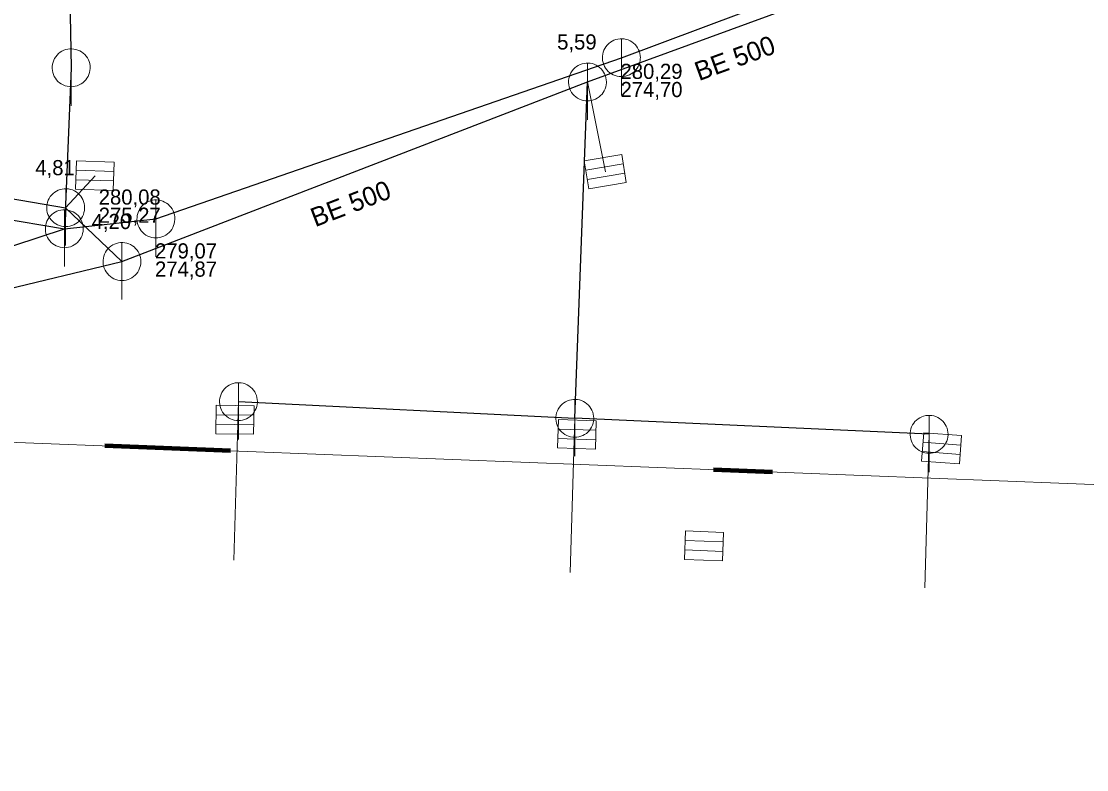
# Model space of a CAD drawing. Extents: x -725153 to -724843, y -978146 to -977794.
# Drawn here: x -725015.4 to -724959.2, y -977881.9 to -977842.4 of the extents above; entities that cross this region are included whole.
import ezdxf

# ---------------------------------------------------------------- set-up
doc = ezdxf.new("R2010")
doc.units = 0
doc.header["$LTSCALE"] = 0.32
doc.layers.add('1', color=7, linetype='Continuous')
for name, color, linetype, lineweight in [('11', 7, 'Continuous', 13), ('13', 7, 'Continuous', 13), ('14', 7, 'Continuous', 25), ('22', 7, 'Continuous', 13), ('3', 7, 'Continuous', 106)]:
    doc.layers.add(name, color=color, linetype=linetype, lineweight=lineweight)

msp = doc.modelspace()

# ---------------------------------------------------------------- linework, layer by layer
at = {"layer": '11'}
for p, q in [((-724984.587, -977850.34), (-724985.539, -977845.6)), ((-725011.522, -977850.547), (-725013.07, -977852.23)), ((-725004.203, -977870.821), (-725003.953, -977862.46)), ((-724986.446, -977871.468), (-724986.209, -977863.341)), ((-724967.733, -977872.279), (-724967.516, -977864.182))]:
    msp.add_line(p, q, dxfattribs=at)
at = {"layer": '13'}
msp.add_lwpolyline([(-724953.059, -977881.873), (-724953.002, -977867.059), (-725028.727, -977864.108)], dxfattribs=at)
at = {"layer": '14'}
for p, q in [((-725013.329, -977813.52), (-725012.78, -977844.85)), ((-724983.75, -977844.32), (-724941.885, -977828.658)), ((-725012.78, -977844.85), (-725013.14, -977853.34)), ((-725042.36, -977847.23), (-725013.07, -977852.23)), ((-725042.11, -977848.46), (-725013.14, -977853.34)), ((-725029.859, -977859.828), (-725010.1, -977855.07)), ((-725003.953, -977862.46), (-724986.209, -977863.341))]:
    msp.add_line(p, q, dxfattribs=at)
for points in [[(-724985.54, -977845.6), (-724969.507, -977839.725), (-724959.646, -977836.111)], [(-725013.14, -977853.34), (-725008.31, -977852.82), (-724983.75, -977844.32)], [(-725013.07, -977852.23), (-725010.1, -977855.07), (-724985.54, -977845.6)], [(-724967.516, -977864.182), (-724986.209, -977863.341), (-724985.54, -977845.6)], [(-725065.126, -977858.647), (-725045.825, -977859.261), (-725028.018, -977858.237), (-725013.14, -977853.34)]]:
    msp.add_lwpolyline(points, dxfattribs=at)
at = {"layer": '22'}
for p, q in [((-724983.75, -977846.32), (-724983.749, -977843.32)), ((-725012.78, -977846.85), (-725012.779, -977843.85)), ((-724985.54, -977847.6), (-724985.539, -977844.6)), ((-724985.626, -977850.253), (-724983.653, -977849.924)), ((-725012.54, -977850.757), (-725010.541, -977850.822)), ((-725012.524, -977850.257), (-725010.525, -977850.322)), ((-724985.544, -977850.746), (-724983.571, -977850.417)), ((-725013.07, -977854.23), (-725013.069, -977851.23)), ((-725008.31, -977854.82), (-725008.309, -977851.82)), ((-725013.14, -977855.34), (-725013.139, -977852.34)), ((-725010.1, -977857.07), (-725010.099, -977854.07)), ((-725003.953, -977864.46), (-725003.952, -977861.46)), ((-724986.209, -977865.341), (-724986.208, -977862.341)), ((-725005.139, -977863.151), (-725003.139, -977863.177)), ((-725005.146, -977863.651), (-725003.146, -977863.677)), ((-724967.516, -977866.182), (-724967.515, -977863.182)), ((-724987.09, -977863.905), (-724985.091, -977863.968)), ((-724987.106, -977864.405), (-724985.107, -977864.468)), ((-724967.839, -977864.6), (-724965.844, -977864.749)), ((-724967.876, -977865.099), (-724965.881, -977865.248)), ((-724980.383, -977869.782), (-724978.384, -977869.86)), ((-724980.402, -977870.281), (-724978.404, -977870.36))]:
    msp.add_line(p, q, dxfattribs=at)
for points in [[(-724982.75, -977844.32), (-724982.755, -977844.211), (-724982.773, -977844.103), (-724982.803, -977843.997), (-724982.843, -977843.896), (-724982.895, -977843.799), (-724982.957, -977843.709), (-724983.029, -977843.626), (-724983.109, -977843.552), (-724983.197, -977843.486), (-724983.291, -977843.431), (-724983.391, -977843.386), (-724983.496, -977843.353), (-724983.603, -977843.331), (-724983.712, -977843.321), (-724983.822, -977843.323), (-724983.93, -977843.337), (-724984.037, -977843.362), (-724984.14, -977843.399), (-724984.238, -977843.448), (-724984.33, -977843.506), (-724984.416, -977843.575), (-724984.493, -977843.652), (-724984.562, -977843.738), (-724984.621, -977843.83), (-724984.669, -977843.928), (-724984.706, -977844.031), (-724984.732, -977844.138), (-724984.746, -977844.246), (-724984.749, -977844.356), (-724984.739, -977844.465), (-724984.718, -977844.572), (-724984.684, -977844.676), (-724984.64, -977844.776), (-724984.585, -977844.871), (-724984.519, -977844.959), (-724984.445, -977845.039), (-724984.362, -977845.111), (-724984.272, -977845.173), (-724984.176, -977845.225), (-724984.074, -977845.266), (-724983.969, -977845.296), (-724983.861, -977845.314), (-724983.751, -977845.32), (-724983.642, -977845.314), (-724983.534, -977845.296), (-724983.429, -977845.267), (-724983.327, -977845.226), (-724983.23, -977845.174), (-724983.14, -977845.112), (-724983.057, -977845.041), (-724982.982, -977844.961), (-724982.917, -977844.873), (-724982.861, -977844.779), (-724982.817, -977844.679), (-724982.783, -977844.575), (-724982.761, -977844.467), (-724982.751, -977844.358)], [(-725011.78, -977844.85), (-725011.785, -977844.741), (-725011.803, -977844.633), (-725011.833, -977844.527), (-725011.873, -977844.426), (-725011.925, -977844.329), (-725011.987, -977844.239), (-725012.059, -977844.156), (-725012.139, -977844.082), (-725012.227, -977844.016), (-725012.321, -977843.961), (-725012.421, -977843.916), (-725012.526, -977843.883), (-725012.633, -977843.861), (-725012.742, -977843.851), (-725012.852, -977843.853), (-725012.96, -977843.867), (-725013.067, -977843.892), (-725013.17, -977843.929), (-725013.268, -977843.978), (-725013.36, -977844.036), (-725013.446, -977844.105), (-725013.523, -977844.182), (-725013.592, -977844.268), (-725013.651, -977844.36), (-725013.699, -977844.458), (-725013.736, -977844.561), (-725013.762, -977844.668), (-725013.776, -977844.776), (-725013.779, -977844.886), (-725013.769, -977844.995), (-725013.748, -977845.102), (-725013.714, -977845.206), (-725013.67, -977845.306), (-725013.615, -977845.401), (-725013.549, -977845.489), (-725013.475, -977845.569), (-725013.392, -977845.641), (-725013.302, -977845.703), (-725013.206, -977845.755), (-725013.104, -977845.796), (-725012.999, -977845.826), (-725012.891, -977845.844), (-725012.781, -977845.85), (-725012.672, -977845.844), (-725012.564, -977845.826), (-725012.459, -977845.797), (-725012.357, -977845.756), (-725012.26, -977845.704), (-725012.17, -977845.642), (-725012.087, -977845.571), (-725012.012, -977845.491), (-725011.947, -977845.403), (-725011.891, -977845.309), (-725011.847, -977845.209), (-725011.813, -977845.105), (-725011.791, -977844.997), (-725011.781, -977844.888)], [(-724984.54, -977845.6), (-724984.545, -977845.491), (-724984.563, -977845.383), (-724984.593, -977845.277), (-724984.633, -977845.176), (-724984.685, -977845.079), (-724984.747, -977844.989), (-724984.819, -977844.906), (-724984.899, -977844.832), (-724984.987, -977844.766), (-724985.081, -977844.711), (-724985.181, -977844.666), (-724985.286, -977844.633), (-724985.393, -977844.611), (-724985.502, -977844.601), (-724985.612, -977844.603), (-724985.72, -977844.617), (-724985.827, -977844.642), (-724985.93, -977844.679), (-724986.028, -977844.728), (-724986.12, -977844.786), (-724986.206, -977844.855), (-724986.283, -977844.932), (-724986.352, -977845.018), (-724986.411, -977845.11), (-724986.459, -977845.208), (-724986.496, -977845.311), (-724986.522, -977845.418), (-724986.536, -977845.526), (-724986.539, -977845.636), (-724986.529, -977845.745), (-724986.508, -977845.852), (-724986.474, -977845.956), (-724986.43, -977846.056), (-724986.375, -977846.151), (-724986.309, -977846.239), (-724986.235, -977846.319), (-724986.152, -977846.391), (-724986.062, -977846.453), (-724985.966, -977846.505), (-724985.864, -977846.546), (-724985.759, -977846.576), (-724985.651, -977846.594), (-724985.541, -977846.6), (-724985.432, -977846.594), (-724985.324, -977846.576), (-724985.219, -977846.547), (-724985.117, -977846.506), (-724985.02, -977846.454), (-724984.93, -977846.392), (-724984.847, -977846.321), (-724984.772, -977846.241), (-724984.707, -977846.153), (-724984.651, -977846.059), (-724984.607, -977845.959), (-724984.573, -977845.855), (-724984.551, -977845.747), (-724984.541, -977845.638)], [(-724985.708, -977849.76), (-724983.735, -977849.431), (-724983.489, -977850.91), (-724985.462, -977851.239)], [(-725012.507, -977849.758), (-725010.509, -977849.822), (-725010.557, -977851.322), (-725012.556, -977851.257)], [(-725012.07, -977852.23), (-725012.075, -977852.121), (-725012.093, -977852.013), (-725012.123, -977851.907), (-725012.163, -977851.806), (-725012.215, -977851.709), (-725012.277, -977851.619), (-725012.349, -977851.536), (-725012.429, -977851.462), (-725012.517, -977851.396), (-725012.611, -977851.341), (-725012.711, -977851.296), (-725012.816, -977851.263), (-725012.923, -977851.241), (-725013.032, -977851.231), (-725013.142, -977851.233), (-725013.25, -977851.247), (-725013.357, -977851.272), (-725013.46, -977851.309), (-725013.558, -977851.358), (-725013.65, -977851.416), (-725013.736, -977851.485), (-725013.813, -977851.562), (-725013.882, -977851.648), (-725013.941, -977851.74), (-725013.989, -977851.838), (-725014.026, -977851.941), (-725014.052, -977852.048), (-725014.066, -977852.156), (-725014.069, -977852.266), (-725014.059, -977852.375), (-725014.038, -977852.482), (-725014.004, -977852.586), (-725013.96, -977852.686), (-725013.905, -977852.781), (-725013.839, -977852.869), (-725013.765, -977852.949), (-725013.682, -977853.021), (-725013.592, -977853.083), (-725013.496, -977853.135), (-725013.394, -977853.176), (-725013.289, -977853.206), (-725013.181, -977853.224), (-725013.071, -977853.23), (-725012.962, -977853.224), (-725012.854, -977853.206), (-725012.749, -977853.177), (-725012.647, -977853.136), (-725012.55, -977853.084), (-725012.46, -977853.022), (-725012.377, -977852.951), (-725012.302, -977852.871), (-725012.237, -977852.783), (-725012.181, -977852.689), (-725012.137, -977852.589), (-725012.103, -977852.485), (-725012.081, -977852.377), (-725012.071, -977852.268)], [(-725007.31, -977852.82), (-725007.315, -977852.711), (-725007.333, -977852.603), (-725007.363, -977852.497), (-725007.403, -977852.396), (-725007.455, -977852.299), (-725007.517, -977852.209), (-725007.589, -977852.126), (-725007.669, -977852.052), (-725007.757, -977851.986), (-725007.851, -977851.931), (-725007.951, -977851.886), (-725008.056, -977851.853), (-725008.163, -977851.831), (-725008.272, -977851.821), (-725008.382, -977851.823), (-725008.49, -977851.837), (-725008.597, -977851.862), (-725008.7, -977851.899), (-725008.798, -977851.948), (-725008.89, -977852.006), (-725008.976, -977852.075), (-725009.053, -977852.152), (-725009.122, -977852.238), (-725009.181, -977852.33), (-725009.229, -977852.428), (-725009.266, -977852.531), (-725009.292, -977852.638), (-725009.306, -977852.746), (-725009.309, -977852.856), (-725009.299, -977852.965), (-725009.278, -977853.072), (-725009.244, -977853.176), (-725009.2, -977853.276), (-725009.145, -977853.371), (-725009.079, -977853.459), (-725009.005, -977853.539), (-725008.922, -977853.611), (-725008.832, -977853.673), (-725008.736, -977853.725), (-725008.634, -977853.766), (-725008.529, -977853.796), (-725008.421, -977853.814), (-725008.311, -977853.82), (-725008.202, -977853.814), (-725008.094, -977853.796), (-725007.989, -977853.767), (-725007.887, -977853.726), (-725007.79, -977853.674), (-725007.7, -977853.612), (-725007.617, -977853.541), (-725007.542, -977853.461), (-725007.477, -977853.373), (-725007.421, -977853.279), (-725007.377, -977853.179), (-725007.343, -977853.075), (-725007.321, -977852.967), (-725007.311, -977852.858)], [(-725012.14, -977853.34), (-725012.145, -977853.231), (-725012.163, -977853.123), (-725012.193, -977853.017), (-725012.233, -977852.916), (-725012.285, -977852.819), (-725012.347, -977852.729), (-725012.419, -977852.646), (-725012.499, -977852.572), (-725012.587, -977852.506), (-725012.681, -977852.451), (-725012.781, -977852.406), (-725012.886, -977852.373), (-725012.993, -977852.351), (-725013.102, -977852.341), (-725013.212, -977852.343), (-725013.32, -977852.357), (-725013.427, -977852.382), (-725013.53, -977852.419), (-725013.628, -977852.468), (-725013.72, -977852.526), (-725013.806, -977852.595), (-725013.883, -977852.672), (-725013.952, -977852.758), (-725014.011, -977852.85), (-725014.059, -977852.948), (-725014.096, -977853.051), (-725014.122, -977853.158), (-725014.136, -977853.266), (-725014.139, -977853.376), (-725014.129, -977853.485), (-725014.108, -977853.592), (-725014.074, -977853.696), (-725014.03, -977853.796), (-725013.975, -977853.891), (-725013.909, -977853.979), (-725013.835, -977854.059), (-725013.752, -977854.131), (-725013.662, -977854.193), (-725013.566, -977854.245), (-725013.464, -977854.286), (-725013.359, -977854.316), (-725013.251, -977854.334), (-725013.141, -977854.34), (-725013.032, -977854.334), (-725012.924, -977854.316), (-725012.819, -977854.287), (-725012.717, -977854.246), (-725012.62, -977854.194), (-725012.53, -977854.132), (-725012.447, -977854.061), (-725012.372, -977853.981), (-725012.307, -977853.893), (-725012.251, -977853.799), (-725012.207, -977853.699), (-725012.173, -977853.595), (-725012.151, -977853.487), (-725012.141, -977853.378)], [(-725009.1, -977855.07), (-725009.105, -977854.961), (-725009.123, -977854.853), (-725009.153, -977854.747), (-725009.193, -977854.646), (-725009.245, -977854.549), (-725009.307, -977854.459), (-725009.379, -977854.376), (-725009.459, -977854.302), (-725009.547, -977854.236), (-725009.641, -977854.181), (-725009.741, -977854.136), (-725009.846, -977854.103), (-725009.953, -977854.081), (-725010.062, -977854.071), (-725010.172, -977854.073), (-725010.28, -977854.087), (-725010.387, -977854.112), (-725010.49, -977854.149), (-725010.588, -977854.198), (-725010.68, -977854.256), (-725010.766, -977854.325), (-725010.843, -977854.402), (-725010.912, -977854.488), (-725010.971, -977854.58), (-725011.019, -977854.678), (-725011.056, -977854.781), (-725011.082, -977854.888), (-725011.096, -977854.996), (-725011.099, -977855.106), (-725011.089, -977855.215), (-725011.068, -977855.322), (-725011.034, -977855.426), (-725010.99, -977855.526), (-725010.935, -977855.621), (-725010.869, -977855.709), (-725010.795, -977855.789), (-725010.712, -977855.861), (-725010.622, -977855.923), (-725010.526, -977855.975), (-725010.424, -977856.016), (-725010.319, -977856.046), (-725010.211, -977856.064), (-725010.101, -977856.07), (-725009.992, -977856.064), (-725009.884, -977856.046), (-725009.779, -977856.017), (-725009.677, -977855.976), (-725009.58, -977855.924), (-725009.49, -977855.862), (-725009.407, -977855.791), (-725009.332, -977855.711), (-725009.267, -977855.623), (-725009.211, -977855.529), (-725009.167, -977855.429), (-725009.133, -977855.325), (-725009.111, -977855.217), (-725009.101, -977855.108)], [(-725002.953, -977862.46), (-725002.958, -977862.351), (-725002.976, -977862.243), (-725003.006, -977862.137), (-725003.046, -977862.036), (-725003.098, -977861.939), (-725003.16, -977861.849), (-725003.232, -977861.766), (-725003.312, -977861.692), (-725003.4, -977861.626), (-725003.494, -977861.571), (-725003.594, -977861.526), (-725003.699, -977861.493), (-725003.806, -977861.471), (-725003.915, -977861.461), (-725004.025, -977861.463), (-725004.133, -977861.477), (-725004.24, -977861.502), (-725004.343, -977861.539), (-725004.441, -977861.588), (-725004.533, -977861.646), (-725004.619, -977861.715), (-725004.696, -977861.792), (-725004.765, -977861.878), (-725004.824, -977861.97), (-725004.872, -977862.068), (-725004.909, -977862.171), (-725004.935, -977862.278), (-725004.949, -977862.386), (-725004.952, -977862.496), (-725004.942, -977862.605), (-725004.921, -977862.712), (-725004.887, -977862.816), (-725004.843, -977862.916), (-725004.788, -977863.011), (-725004.722, -977863.099), (-725004.648, -977863.179), (-725004.565, -977863.251), (-725004.475, -977863.313), (-725004.379, -977863.365), (-725004.277, -977863.406), (-725004.172, -977863.436), (-725004.064, -977863.454), (-725003.954, -977863.46), (-725003.845, -977863.454), (-725003.737, -977863.436), (-725003.632, -977863.407), (-725003.53, -977863.366), (-725003.433, -977863.314), (-725003.343, -977863.252), (-725003.26, -977863.181), (-725003.185, -977863.101), (-725003.12, -977863.013), (-725003.064, -977862.919), (-725003.02, -977862.819), (-725002.986, -977862.715), (-725002.964, -977862.607), (-725002.954, -977862.498)], [(-724985.209, -977863.341), (-724985.214, -977863.232), (-724985.232, -977863.124), (-724985.262, -977863.018), (-724985.302, -977862.917), (-724985.354, -977862.82), (-724985.416, -977862.73), (-724985.488, -977862.647), (-724985.568, -977862.573), (-724985.656, -977862.507), (-724985.75, -977862.452), (-724985.85, -977862.407), (-724985.955, -977862.374), (-724986.062, -977862.352), (-724986.171, -977862.342), (-724986.281, -977862.344), (-724986.389, -977862.358), (-724986.496, -977862.383), (-724986.599, -977862.42), (-724986.697, -977862.469), (-724986.789, -977862.527), (-724986.875, -977862.596), (-724986.952, -977862.673), (-724987.021, -977862.759), (-724987.08, -977862.851), (-724987.128, -977862.949), (-724987.165, -977863.052), (-724987.191, -977863.159), (-724987.205, -977863.267), (-724987.208, -977863.377), (-724987.198, -977863.486), (-724987.177, -977863.593), (-724987.143, -977863.697), (-724987.099, -977863.797), (-724987.044, -977863.892), (-724986.978, -977863.98), (-724986.904, -977864.06), (-724986.821, -977864.132), (-724986.731, -977864.194), (-724986.635, -977864.246), (-724986.533, -977864.287), (-724986.428, -977864.317), (-724986.32, -977864.335), (-724986.21, -977864.341), (-724986.101, -977864.335), (-724985.993, -977864.317), (-724985.888, -977864.288), (-724985.786, -977864.247), (-724985.689, -977864.195), (-724985.599, -977864.133), (-724985.516, -977864.062), (-724985.441, -977863.982), (-724985.376, -977863.894), (-724985.32, -977863.8), (-724985.276, -977863.7), (-724985.242, -977863.596), (-724985.22, -977863.488), (-724985.21, -977863.379)], [(-725005.133, -977862.651), (-725003.133, -977862.677), (-725003.152, -977864.177), (-725005.152, -977864.151)], [(-724987.074, -977863.405), (-724985.075, -977863.469), (-724985.123, -977864.968), (-724987.122, -977864.905)], [(-724966.516, -977864.182), (-724966.521, -977864.073), (-724966.539, -977863.965), (-724966.569, -977863.859), (-724966.609, -977863.758), (-724966.661, -977863.661), (-724966.723, -977863.571), (-724966.795, -977863.488), (-724966.875, -977863.414), (-724966.963, -977863.348), (-724967.057, -977863.293), (-724967.157, -977863.248), (-724967.262, -977863.215), (-724967.369, -977863.193), (-724967.478, -977863.183), (-724967.588, -977863.185), (-724967.696, -977863.199), (-724967.803, -977863.224), (-724967.906, -977863.261), (-724968.004, -977863.31), (-724968.096, -977863.368), (-724968.182, -977863.437), (-724968.259, -977863.514), (-724968.328, -977863.6), (-724968.387, -977863.692), (-724968.435, -977863.79), (-724968.472, -977863.893), (-724968.498, -977864), (-724968.512, -977864.108), (-724968.515, -977864.218), (-724968.505, -977864.327), (-724968.484, -977864.434), (-724968.45, -977864.538), (-724968.406, -977864.638), (-724968.351, -977864.733), (-724968.285, -977864.821), (-724968.211, -977864.901), (-724968.128, -977864.973), (-724968.038, -977865.035), (-724967.942, -977865.087), (-724967.84, -977865.128), (-724967.735, -977865.158), (-724967.627, -977865.176), (-724967.517, -977865.182), (-724967.408, -977865.176), (-724967.3, -977865.158), (-724967.195, -977865.129), (-724967.093, -977865.088), (-724966.996, -977865.036), (-724966.906, -977864.974), (-724966.823, -977864.903), (-724966.748, -977864.823), (-724966.683, -977864.735), (-724966.627, -977864.641), (-724966.583, -977864.541), (-724966.549, -977864.437), (-724966.527, -977864.329), (-724966.517, -977864.22)], [(-724967.801, -977864.102), (-724965.807, -977864.251), (-724965.919, -977865.747), (-724967.913, -977865.598)], [(-724980.363, -977869.282), (-724978.365, -977869.36), (-724978.423, -977870.859), (-724980.422, -977870.781)]]:
    msp.add_lwpolyline(points, close=True, dxfattribs=at)
at = {"layer": '3'}
for p, q in [((-725004.382, -977865.058), (-725011.003, -977864.8)), ((-724975.78, -977866.172), (-724978.888, -977866.051))]:
    msp.add_line(p, q, dxfattribs=at)
at = {"layer": '3', "lineweight": 100}
for p, q in [((-725004.382, -977865.058), (-725011.003, -977864.8)), ((-724975.78, -977866.172), (-724978.888, -977866.051))]:
    msp.add_line(p, q, dxfattribs=at)

# ---------------------------------------------------------------- texts
at = {"layer": '1'}
for s, p in [('5,59', (-724987.139, -977843.888)), ('4,81', (-725014.67, -977850.518)), ('4,20', (-725011.699, -977853.358))]:
    msp.add_text(s, height=0.8, dxfattribs=at).set_placement(p)
for rotation, p in [(20, (-724979.656, -977845.558)), (21, (-724999.904, -977853.265))]:
    msp.add_text('BE 500', height=1, rotation=rotation, dxfattribs=at).set_placement(p)
at = {"layer": '22'}
for s, p in [('280,29', (-724983.797, -977845.439)), ('274,70', (-724983.797, -977846.399)), ('280,08', (-725011.327, -977852.069)), ('275,27', (-725011.327, -977853.029)), ('279,07', (-725008.357, -977854.91)), ('274,87', (-725008.357, -977855.87))]:
    msp.add_text(s, height=0.8, dxfattribs=at).set_placement(p)

doc.saveas('drawing.dxf')
